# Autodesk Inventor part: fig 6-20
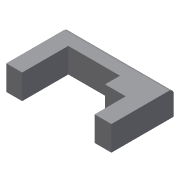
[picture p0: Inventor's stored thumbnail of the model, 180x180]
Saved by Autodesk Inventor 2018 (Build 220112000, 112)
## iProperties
Created: 2010-08
Part Number: fig 6-20
Document SubType Name: Modeling
Designer: CADSoft
Density: 1 g/cm^3
Material: Generic
Appearance: Default
Author: CADSoft
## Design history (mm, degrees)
sketch "Sketch1"
  geometry: L1 (-25.394, 25.152)-(17.03, 25.152); L2 (17.03, 25.152)-(17.03, 0); L3 (-25.394, 0)-(-25.394, 25.152); L4 (10.242, 0)-(10.242, 12.576); L5 (10.242, 12.576)-(1.879, 12.576); L6 (1.879, 12.576)-(1.879, 18.606); L7 (1.879, 18.606)-(-18.97, 18.606); L8 (-18.97, 18.606)-(-18.97, 0); L9 (17.03, 0)-(10.242, 0); L10 (-18.97, 0)-(-25.394, 0); 1 further point
  constraints: 20 end point, 6 parallel, 4 perpendicular, 1 horizontal
extrude "Extrusion1" new body sketch "Sketch1" distance "d0" = 10; taper "d1" = 0 deg
fillet "Fillet1" dims "d2" = 2
body "Solid1"
